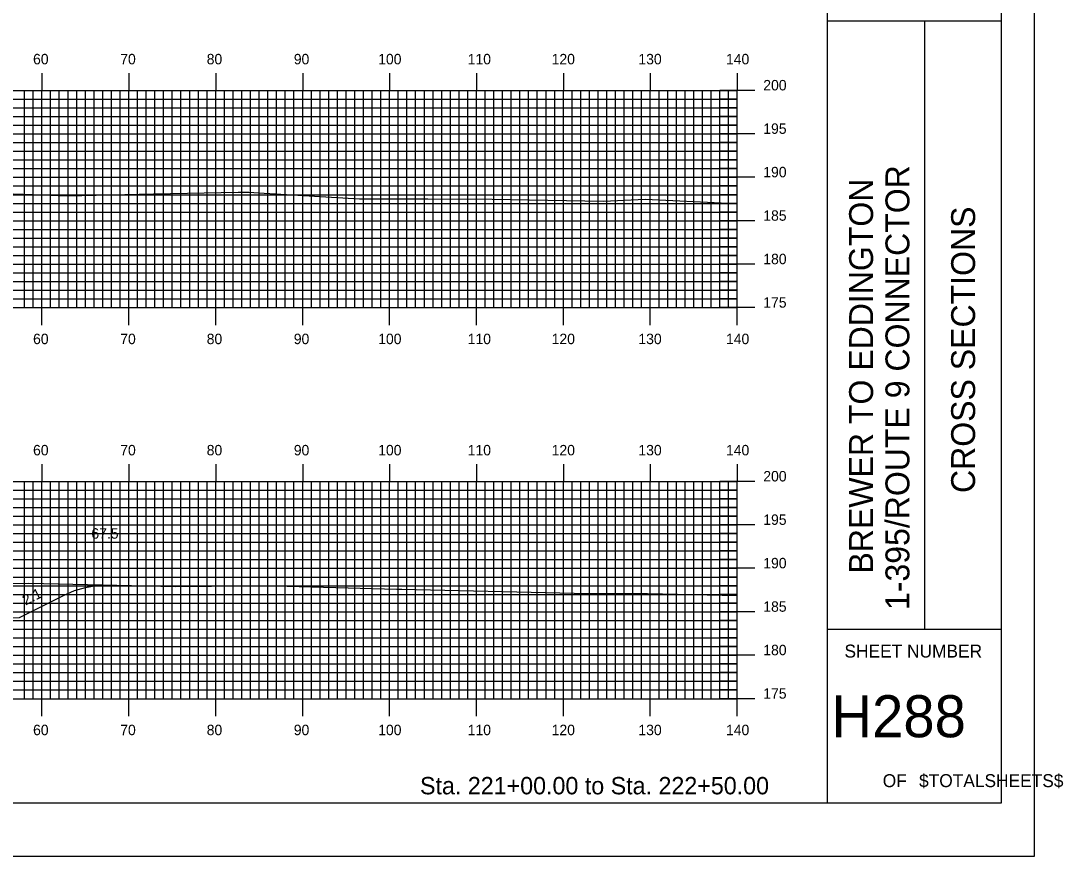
# Model space of a CAD drawing. Extents: x 1797601 to 1797944, y 442591 to 442811.
# Drawn here: x 1797824 to 1797943.9, y 442590.5 to 442686.7 of the extents above; entities that cross this region are included whole.
import ezdxf

# ---------------------------------------------------------------- set-up
doc = ezdxf.new("R2010")
doc.units = 0
for name, color, linetype in [('ANNOTATION', 7, 'Continuous'), ('BORDER', 7, 'Continuous'), ('D_Roadway_Centerline', 7, 'Continuous'), ('D_Roadway_SlopeLines', 7, 'Continuous'), ('D_Text_Standard', 7, 'Continuous'), ('H_V ANNOTATION', 7, 'Continuous'), ('MAJOR', 7, 'Continuous'), ('MINOR', 7, 'Continuous'), ('PLOT BOUNDARY', 7, 'Continuous'), ('S_Roadway_Centerline', 7, 'Continuous')]:
    doc.layers.add(name, color=color, linetype=linetype)

msp = doc.modelspace()

# ---------------------------------------------------------------- linework, layer by layer
at = {"layer": 'BORDER'}
for p, q in [((1797916.84, 442596.67), (1797916.84, 442806.67)), ((1797916.84, 442686.67), (1797936.84, 442686.67)), ((1797928.03, 442616.67), (1797928.03, 442686.67)), ((1797916.84, 442616.67), (1797936.84, 442616.67))]:
    msp.add_line(p, q, dxfattribs=at)
msp.add_lwpolyline([(1797616.84, 442596.67), (1797936.84, 442596.67), (1797936.84, 442806.67), (1797616.84, 442806.67)], close=True, dxfattribs=at)
at = {"layer": 'D_Roadway_Centerline'}
msp.add_lwpolyline([(1797698.94, 442623.65), (1797700.19, 442623.55), (1797701.44, 442623.31), (1797702.69, 442622.91), (1797703.94, 442622.36), (1797711.73, 442618.47), (1797721.64, 442618.37), (1797732.27, 442614.83), (1797736.27, 442615.83), (1797746.44, 442618.37), (1797754.44, 442618.69), (1797766.44, 442618.45), (1797778.44, 442618.21), (1797786.44, 442617.89), (1797796.62, 442615.35), (1797800.62, 442614.35), (1797811.25, 442617.89), (1797823.86, 442618.01), (1797828.94, 442620.56), (1797830.19, 442621.1), (1797831.44, 442621.48), (1797832.69, 442621.7), (1797833.94, 442621.75)], dxfattribs=at)
at = {"layer": 'D_Roadway_SlopeLines'}
msp.add_lwpolyline([(1797811.25, 442617.89), (1797823.86, 442618.01), (1797828.94, 442620.56), (1797830.19, 442621.1), (1797831.44, 442621.48), (1797832.69, 442621.7), (1797833.94, 442621.75)], dxfattribs=at)
at = {"layer": 'MAJOR'}
for p, q in [((1797826.44, 442680.67), (1797826.44, 442678.67)), ((1797836.44, 442680.67), (1797836.44, 442678.67)), ((1797846.44, 442680.67), (1797846.44, 442678.67)), ((1797856.44, 442680.67), (1797856.44, 442678.67)), ((1797866.44, 442680.67), (1797866.44, 442678.67)), ((1797876.44, 442680.67), (1797876.44, 442678.67)), ((1797886.44, 442680.67), (1797886.44, 442678.67)), ((1797896.44, 442680.67), (1797896.44, 442678.67)), ((1797906.44, 442680.67), (1797906.44, 442678.67)), ((1797626.44, 442678.67), (1797906.44, 442678.67)), ((1797626.44, 442678.67), (1797906.44, 442678.67)), ((1797826.44, 442653.67), (1797826.44, 442678.67)), ((1797836.44, 442653.67), (1797836.44, 442678.67)), ((1797846.44, 442653.67), (1797846.44, 442678.67)), ((1797856.44, 442653.67), (1797856.44, 442678.67)), ((1797866.44, 442653.67), (1797866.44, 442678.67)), ((1797876.44, 442653.67), (1797876.44, 442678.67)), ((1797886.44, 442653.67), (1797886.44, 442678.67)), ((1797896.44, 442653.67), (1797896.44, 442678.67)), ((1797908.45, 442678.67), (1797904.44, 442678.67)), ((1797906.44, 442653.67), (1797906.44, 442678.67)), ((1797906.44, 442653.67), (1797906.44, 442678.67)), ((1797626.44, 442673.67), (1797906.44, 442673.67)), ((1797908.45, 442673.67), (1797904.44, 442673.67)), ((1797626.44, 442668.67), (1797906.44, 442668.67)), ((1797908.45, 442668.67), (1797904.44, 442668.67)), ((1797626.44, 442663.67), (1797906.44, 442663.67)), ((1797908.45, 442663.67), (1797904.44, 442663.67)), ((1797626.44, 442658.67), (1797906.44, 442658.67)), ((1797908.45, 442658.67), (1797904.44, 442658.67)), ((1797626.44, 442653.67), (1797906.44, 442653.67)), ((1797626.44, 442653.67), (1797906.44, 442653.67)), ((1797826.44, 442651.66), (1797826.44, 442653.67)), ((1797836.44, 442651.66), (1797836.44, 442653.67)), ((1797846.44, 442651.66), (1797846.44, 442653.67)), ((1797856.44, 442651.66), (1797856.44, 442653.67)), ((1797866.44, 442651.66), (1797866.44, 442653.67)), ((1797876.44, 442651.66), (1797876.44, 442653.67)), ((1797886.44, 442651.66), (1797886.44, 442653.67)), ((1797896.44, 442651.66), (1797896.44, 442653.67)), ((1797908.45, 442653.67), (1797904.44, 442653.67)), ((1797906.44, 442651.66), (1797906.44, 442653.67)), ((1797826.44, 442635.67), (1797826.44, 442633.67)), ((1797836.44, 442635.67), (1797836.44, 442633.67)), ((1797846.44, 442635.67), (1797846.44, 442633.67)), ((1797856.44, 442635.67), (1797856.44, 442633.67)), ((1797866.44, 442635.67), (1797866.44, 442633.67)), ((1797876.44, 442635.67), (1797876.44, 442633.67)), ((1797886.44, 442635.67), (1797886.44, 442633.67)), ((1797896.44, 442635.67), (1797896.44, 442633.67)), ((1797906.44, 442635.67), (1797906.44, 442633.67)), ((1797626.44, 442633.67), (1797906.44, 442633.67)), ((1797626.44, 442633.67), (1797906.44, 442633.67)), ((1797826.44, 442608.67), (1797826.44, 442633.67)), ((1797836.44, 442608.67), (1797836.44, 442633.67)), ((1797846.44, 442608.67), (1797846.44, 442633.67)), ((1797856.44, 442608.67), (1797856.44, 442633.67)), ((1797866.44, 442608.67), (1797866.44, 442633.67)), ((1797876.44, 442608.67), (1797876.44, 442633.67)), ((1797886.44, 442608.67), (1797886.44, 442633.67)), ((1797896.44, 442608.67), (1797896.44, 442633.67)), ((1797908.45, 442633.67), (1797904.44, 442633.67)), ((1797906.44, 442608.67), (1797906.44, 442633.67)), ((1797906.44, 442608.67), (1797906.44, 442633.67)), ((1797626.44, 442628.67), (1797906.44, 442628.67)), ((1797908.45, 442628.67), (1797904.44, 442628.67)), ((1797626.44, 442623.67), (1797906.44, 442623.67)), ((1797908.45, 442623.67), (1797904.44, 442623.67)), ((1797626.44, 442618.67), (1797906.44, 442618.67)), ((1797908.45, 442618.67), (1797904.44, 442618.67)), ((1797626.44, 442613.67), (1797906.44, 442613.67)), ((1797908.45, 442613.67), (1797904.44, 442613.67)), ((1797626.44, 442608.67), (1797906.44, 442608.67)), ((1797626.44, 442608.67), (1797906.44, 442608.67)), ((1797826.44, 442606.66), (1797826.44, 442608.67)), ((1797836.44, 442606.66), (1797836.44, 442608.67)), ((1797846.44, 442606.66), (1797846.44, 442608.67)), ((1797856.44, 442606.66), (1797856.44, 442608.67)), ((1797866.44, 442606.66), (1797866.44, 442608.67)), ((1797876.44, 442606.66), (1797876.44, 442608.67)), ((1797886.44, 442606.66), (1797886.44, 442608.67)), ((1797896.44, 442606.66), (1797896.44, 442608.67)), ((1797908.45, 442608.67), (1797904.44, 442608.67)), ((1797906.44, 442606.66), (1797906.44, 442608.67))]:
    msp.add_line(p, q, dxfattribs=at)
at = {"layer": 'MINOR'}
for p, q in [((1797824.44, 442653.67), (1797824.44, 442678.67)), ((1797825.44, 442653.67), (1797825.44, 442678.67)), ((1797827.44, 442653.67), (1797827.44, 442678.67)), ((1797828.44, 442653.67), (1797828.44, 442678.67)), ((1797829.44, 442653.67), (1797829.44, 442678.67)), ((1797830.44, 442653.67), (1797830.44, 442678.67)), ((1797831.44, 442653.67), (1797831.44, 442678.67)), ((1797832.44, 442653.67), (1797832.44, 442678.67)), ((1797833.44, 442653.67), (1797833.44, 442678.67)), ((1797834.44, 442653.67), (1797834.44, 442678.67)), ((1797835.44, 442653.67), (1797835.44, 442678.67)), ((1797837.44, 442653.67), (1797837.44, 442678.67)), ((1797838.44, 442653.67), (1797838.44, 442678.67)), ((1797839.44, 442653.67), (1797839.44, 442678.67)), ((1797840.44, 442653.67), (1797840.44, 442678.67)), ((1797841.44, 442653.67), (1797841.44, 442678.67)), ((1797842.44, 442653.67), (1797842.44, 442678.67)), ((1797843.44, 442653.67), (1797843.44, 442678.67)), ((1797844.44, 442653.67), (1797844.44, 442678.67)), ((1797845.44, 442653.67), (1797845.44, 442678.67)), ((1797847.44, 442653.67), (1797847.44, 442678.67)), ((1797848.44, 442653.67), (1797848.44, 442678.67)), ((1797849.44, 442653.67), (1797849.44, 442678.67)), ((1797850.44, 442653.67), (1797850.44, 442678.67)), ((1797851.44, 442653.67), (1797851.44, 442678.67)), ((1797852.44, 442653.67), (1797852.44, 442678.67)), ((1797853.44, 442653.67), (1797853.44, 442678.67)), ((1797854.44, 442653.67), (1797854.44, 442678.67)), ((1797855.44, 442653.67), (1797855.44, 442678.67)), ((1797857.44, 442653.67), (1797857.44, 442678.67)), ((1797858.44, 442653.67), (1797858.44, 442678.67)), ((1797859.44, 442653.67), (1797859.44, 442678.67)), ((1797860.44, 442653.67), (1797860.44, 442678.67)), ((1797861.44, 442653.67), (1797861.44, 442678.67)), ((1797862.44, 442653.67), (1797862.44, 442678.67)), ((1797863.44, 442653.67), (1797863.44, 442678.67)), ((1797864.44, 442653.67), (1797864.44, 442678.67)), ((1797865.44, 442653.67), (1797865.44, 442678.67)), ((1797867.44, 442653.67), (1797867.44, 442678.67)), ((1797868.44, 442653.67), (1797868.44, 442678.67)), ((1797869.44, 442653.67), (1797869.44, 442678.67)), ((1797870.44, 442653.67), (1797870.44, 442678.67)), ((1797871.44, 442653.67), (1797871.44, 442678.67)), ((1797872.44, 442653.67), (1797872.44, 442678.67)), ((1797873.44, 442653.67), (1797873.44, 442678.67)), ((1797874.44, 442653.67), (1797874.44, 442678.67)), ((1797875.44, 442653.67), (1797875.44, 442678.67)), ((1797877.44, 442653.67), (1797877.44, 442678.67)), ((1797878.44, 442653.67), (1797878.44, 442678.67)), ((1797879.44, 442653.67), (1797879.44, 442678.67)), ((1797880.44, 442653.67), (1797880.44, 442678.67)), ((1797881.44, 442653.67), (1797881.44, 442678.67)), ((1797882.44, 442653.67), (1797882.44, 442678.67)), ((1797883.44, 442653.67), (1797883.44, 442678.67)), ((1797884.44, 442653.67), (1797884.44, 442678.67)), ((1797885.44, 442653.67), (1797885.44, 442678.67)), ((1797887.44, 442653.67), (1797887.44, 442678.67)), ((1797888.44, 442653.67), (1797888.44, 442678.67)), ((1797889.44, 442653.67), (1797889.44, 442678.67)), ((1797890.44, 442653.67), (1797890.44, 442678.67)), ((1797891.44, 442653.67), (1797891.44, 442678.67)), ((1797892.44, 442653.67), (1797892.44, 442678.67)), ((1797893.44, 442653.67), (1797893.44, 442678.67)), ((1797894.44, 442653.67), (1797894.44, 442678.67)), ((1797895.44, 442653.67), (1797895.44, 442678.67)), ((1797897.44, 442653.67), (1797897.44, 442678.67)), ((1797898.44, 442653.67), (1797898.44, 442678.67)), ((1797899.44, 442653.67), (1797899.44, 442678.67)), ((1797900.44, 442653.67), (1797900.44, 442678.67)), ((1797901.44, 442653.67), (1797901.44, 442678.67)), ((1797902.44, 442653.67), (1797902.44, 442678.67)), ((1797903.44, 442653.67), (1797903.44, 442678.67)), ((1797904.44, 442653.67), (1797904.44, 442678.67)), ((1797905.44, 442653.67), (1797905.44, 442678.67)), ((1797626.44, 442677.67), (1797906.44, 442677.67)), ((1797906.44, 442677.67), (1797904.44, 442677.67)), ((1797626.44, 442676.67), (1797906.44, 442676.67)), ((1797906.44, 442676.67), (1797904.44, 442676.67)), ((1797626.44, 442675.67), (1797906.44, 442675.67)), ((1797626.44, 442674.67), (1797906.44, 442674.67)), ((1797906.44, 442675.67), (1797904.44, 442675.67)), ((1797906.44, 442674.67), (1797904.44, 442674.67)), ((1797626.44, 442672.67), (1797906.44, 442672.67)), ((1797906.44, 442672.67), (1797904.44, 442672.67)), ((1797626.44, 442671.67), (1797906.44, 442671.67)), ((1797906.44, 442671.67), (1797904.44, 442671.67)), ((1797626.44, 442670.67), (1797906.44, 442670.67)), ((1797906.44, 442670.67), (1797904.44, 442670.67)), ((1797626.44, 442669.67), (1797906.44, 442669.67)), ((1797906.44, 442669.67), (1797904.44, 442669.67)), ((1797626.44, 442667.67), (1797906.44, 442667.67)), ((1797906.44, 442667.67), (1797904.44, 442667.67)), ((1797626.44, 442666.67), (1797906.44, 442666.67)), ((1797906.44, 442666.67), (1797904.44, 442666.67)), ((1797626.44, 442665.67), (1797906.44, 442665.67)), ((1797906.44, 442665.67), (1797904.44, 442665.67)), ((1797626.44, 442664.67), (1797906.44, 442664.67)), ((1797906.44, 442664.67), (1797904.44, 442664.67)), ((1797626.44, 442662.67), (1797906.44, 442662.67)), ((1797906.44, 442662.67), (1797904.44, 442662.67)), ((1797626.44, 442661.67), (1797906.44, 442661.67)), ((1797906.44, 442661.67), (1797904.44, 442661.67)), ((1797626.44, 442660.67), (1797906.44, 442660.67)), ((1797906.44, 442660.67), (1797904.44, 442660.67)), ((1797626.44, 442659.67), (1797906.44, 442659.67)), ((1797906.44, 442659.67), (1797904.44, 442659.67)), ((1797626.44, 442657.67), (1797906.44, 442657.67)), ((1797626.44, 442656.67), (1797906.44, 442656.67)), ((1797906.44, 442657.67), (1797904.44, 442657.67)), ((1797906.44, 442656.67), (1797904.44, 442656.67)), ((1797626.44, 442655.67), (1797906.44, 442655.67)), ((1797906.44, 442655.67), (1797904.44, 442655.67)), ((1797626.44, 442654.67), (1797906.44, 442654.67)), ((1797906.44, 442654.67), (1797904.44, 442654.67)), ((1797626.44, 442632.67), (1797906.44, 442632.67)), ((1797824.44, 442608.67), (1797824.44, 442633.67)), ((1797825.44, 442608.67), (1797825.44, 442633.67)), ((1797827.44, 442608.67), (1797827.44, 442633.67)), ((1797828.44, 442608.67), (1797828.44, 442633.67)), ((1797829.44, 442608.67), (1797829.44, 442633.67)), ((1797830.44, 442608.67), (1797830.44, 442633.67)), ((1797831.44, 442608.67), (1797831.44, 442633.67)), ((1797832.44, 442608.67), (1797832.44, 442633.67)), ((1797833.44, 442608.67), (1797833.44, 442633.67)), ((1797834.44, 442608.67), (1797834.44, 442633.67)), ((1797835.44, 442608.67), (1797835.44, 442633.67)), ((1797837.44, 442608.67), (1797837.44, 442633.67)), ((1797838.44, 442608.67), (1797838.44, 442633.67)), ((1797839.44, 442608.67), (1797839.44, 442633.67)), ((1797840.44, 442608.67), (1797840.44, 442633.67)), ((1797841.44, 442608.67), (1797841.44, 442633.67)), ((1797842.44, 442608.67), (1797842.44, 442633.67)), ((1797843.44, 442608.67), (1797843.44, 442633.67)), ((1797844.44, 442608.67), (1797844.44, 442633.67)), ((1797845.44, 442608.67), (1797845.44, 442633.67)), ((1797847.44, 442608.67), (1797847.44, 442633.67)), ((1797848.44, 442608.67), (1797848.44, 442633.67)), ((1797849.44, 442608.67), (1797849.44, 442633.67)), ((1797850.44, 442608.67), (1797850.44, 442633.67)), ((1797851.44, 442608.67), (1797851.44, 442633.67)), ((1797852.44, 442608.67), (1797852.44, 442633.67)), ((1797853.44, 442608.67), (1797853.44, 442633.67)), ((1797854.44, 442608.67), (1797854.44, 442633.67)), ((1797855.44, 442608.67), (1797855.44, 442633.67)), ((1797857.44, 442608.67), (1797857.44, 442633.67)), ((1797858.44, 442608.67), (1797858.44, 442633.67)), ((1797859.44, 442608.67), (1797859.44, 442633.67)), ((1797860.44, 442608.67), (1797860.44, 442633.67)), ((1797861.44, 442608.67), (1797861.44, 442633.67)), ((1797862.44, 442608.67), (1797862.44, 442633.67)), ((1797863.44, 442608.67), (1797863.44, 442633.67)), ((1797864.44, 442608.67), (1797864.44, 442633.67)), ((1797865.44, 442608.67), (1797865.44, 442633.67)), ((1797867.44, 442608.67), (1797867.44, 442633.67)), ((1797868.44, 442608.67), (1797868.44, 442633.67)), ((1797869.44, 442608.67), (1797869.44, 442633.67)), ((1797870.44, 442608.67), (1797870.44, 442633.67)), ((1797871.44, 442608.67), (1797871.44, 442633.67)), ((1797872.44, 442608.67), (1797872.44, 442633.67)), ((1797873.44, 442608.67), (1797873.44, 442633.67)), ((1797874.44, 442608.67), (1797874.44, 442633.67)), ((1797875.44, 442608.67), (1797875.44, 442633.67)), ((1797877.44, 442608.67), (1797877.44, 442633.67)), ((1797878.44, 442608.67), (1797878.44, 442633.67)), ((1797879.44, 442608.67), (1797879.44, 442633.67)), ((1797880.44, 442608.67), (1797880.44, 442633.67)), ((1797881.44, 442608.67), (1797881.44, 442633.67)), ((1797882.44, 442608.67), (1797882.44, 442633.67)), ((1797883.44, 442608.67), (1797883.44, 442633.67)), ((1797884.44, 442608.67), (1797884.44, 442633.67)), ((1797885.44, 442608.67), (1797885.44, 442633.67)), ((1797887.44, 442608.67), (1797887.44, 442633.67)), ((1797888.44, 442608.67), (1797888.44, 442633.67)), ((1797889.44, 442608.67), (1797889.44, 442633.67)), ((1797890.44, 442608.67), (1797890.44, 442633.67)), ((1797891.44, 442608.67), (1797891.44, 442633.67)), ((1797892.44, 442608.67), (1797892.44, 442633.67)), ((1797893.44, 442608.67), (1797893.44, 442633.67)), ((1797894.44, 442608.67), (1797894.44, 442633.67)), ((1797895.44, 442608.67), (1797895.44, 442633.67)), ((1797897.44, 442608.67), (1797897.44, 442633.67)), ((1797898.44, 442608.67), (1797898.44, 442633.67)), ((1797899.44, 442608.67), (1797899.44, 442633.67)), ((1797900.44, 442608.67), (1797900.44, 442633.67)), ((1797901.44, 442608.67), (1797901.44, 442633.67)), ((1797902.44, 442608.67), (1797902.44, 442633.67)), ((1797903.44, 442608.67), (1797903.44, 442633.67)), ((1797904.44, 442608.67), (1797904.44, 442633.67)), ((1797906.44, 442632.67), (1797904.44, 442632.67)), ((1797905.44, 442608.67), (1797905.44, 442633.67)), ((1797626.44, 442631.67), (1797906.44, 442631.67)), ((1797906.44, 442631.67), (1797904.44, 442631.67)), ((1797626.44, 442630.67), (1797906.44, 442630.67)), ((1797906.44, 442630.67), (1797904.44, 442630.67)), ((1797626.44, 442629.67), (1797906.44, 442629.67)), ((1797906.44, 442629.67), (1797904.44, 442629.67)), ((1797626.44, 442627.67), (1797906.44, 442627.67)), ((1797626.44, 442626.67), (1797906.44, 442626.67)), ((1797906.44, 442627.67), (1797904.44, 442627.67)), ((1797906.44, 442626.67), (1797904.44, 442626.67)), ((1797626.44, 442625.67), (1797906.44, 442625.67)), ((1797906.44, 442625.67), (1797904.44, 442625.67)), ((1797626.44, 442624.67), (1797906.44, 442624.67)), ((1797906.44, 442624.67), (1797904.44, 442624.67)), ((1797626.44, 442622.67), (1797906.44, 442622.67)), ((1797906.44, 442622.67), (1797904.44, 442622.67)), ((1797626.44, 442621.67), (1797906.44, 442621.67)), ((1797626.44, 442620.67), (1797906.44, 442620.67)), ((1797906.44, 442621.67), (1797904.44, 442621.67)), ((1797906.44, 442620.67), (1797904.44, 442620.67)), ((1797626.44, 442619.67), (1797906.44, 442619.67)), ((1797906.44, 442619.67), (1797904.44, 442619.67)), ((1797626.44, 442617.67), (1797906.44, 442617.67)), ((1797906.44, 442617.67), (1797904.44, 442617.67)), ((1797626.44, 442616.67), (1797906.44, 442616.67)), ((1797906.44, 442616.67), (1797904.44, 442616.67)), ((1797626.44, 442615.67), (1797906.44, 442615.67)), ((1797626.44, 442614.67), (1797906.44, 442614.67)), ((1797906.44, 442615.67), (1797904.44, 442615.67)), ((1797906.44, 442614.67), (1797904.44, 442614.67)), ((1797626.44, 442612.67), (1797906.44, 442612.67)), ((1797906.44, 442612.67), (1797904.44, 442612.67)), ((1797626.44, 442611.67), (1797906.44, 442611.67)), ((1797906.44, 442611.67), (1797904.44, 442611.67)), ((1797626.44, 442610.67), (1797906.44, 442610.67)), ((1797906.44, 442610.67), (1797904.44, 442610.67)), ((1797626.44, 442609.67), (1797906.44, 442609.67)), ((1797906.44, 442609.67), (1797904.44, 442609.67))]:
    msp.add_line(p, q, dxfattribs=at)
at = {"layer": 'PLOT BOUNDARY'}
msp.add_lwpolyline([(1797600.66, 442590.55), (1797940.66, 442590.55), (1797940.66, 442810.55), (1797600.66, 442810.55)], close=True, dxfattribs=at)
at = {"layer": 'S_Roadway_Centerline'}
for points in [[(1797815.1, 442667.03), (1797826.56, 442666.64), (1797828.3, 442666.58), (1797829.39, 442666.54), (1797839.27, 442666.75), (1797849.03, 442666.94), (1797850.24, 442666.95), (1797852.01, 442666.86), (1797862.99, 442666.2), (1797870.86, 442666.21), (1797878.26, 442666.14), (1797891.05, 442665.93), (1797895.83, 442666.17), (1797905.4, 442665.68), (1797906.44, 442665.67)], [(1797815.49, 442621.88), (1797824.93, 442621.95), (1797841.8, 442621.58), (1797845.94, 442621.6), (1797853.25, 442621.64), (1797867.28, 442621.28), (1797867.57, 442621.29), (1797867.84, 442621.27), (1797887.69, 442620.81), (1797896.11, 442620.76), (1797906.44, 442620.55)]]:
    msp.add_lwpolyline(points, dxfattribs=at)

# ---------------------------------------------------------------- texts
at = {"layer": 'ANNOTATION'}
msp.add_text('2:1', height=1.2, rotation=26.5651, dxfattribs=at).set_placement((1797824.55, 442619.39))
at = {"layer": 'BORDER'}
for s, p in [('1-395/ROUTE 9 CONNECTOR', (1797926.25, 442618.87)), ('BREWER TO EDDINGTON', (1797922.07, 442623.07)), ('CROSS SECTIONS', (1797933.81, 442632.34))]:
    msp.add_text(s, height=2.7557, rotation=90, dxfattribs=at).set_placement(p)
for s, height, p in [('SHEET NUMBER', 1.4905, (1797918.78, 442613.4)), ('H288', 4.839, (1797917.28, 442604.23)), ('OF', 1.491, (1797923.18, 442598.49)), ('$TOTALSHEETS$', 1.4905, (1797927.36, 442598.49))]:
    msp.add_text(s, height=height, dxfattribs=at).set_placement(p)
at = {"layer": 'D_Text_Standard'}
msp.add_text("67.5'", height=1.2, dxfattribs=at).set_placement((1797832.13, 442627.08))
at = {"layer": 'H_V ANNOTATION'}
for s, height, p in [('60', 1.2, (1797825.42, 442681.67)), ('70', 1.2, (1797835.45, 442681.67)), ('80', 1.2, (1797845.4, 442681.67)), ('90', 1.2, (1797855.42, 442681.67)), ('100', 1.2, (1797865.13, 442681.67)), ('110', 1.2, (1797875.43, 442681.67)), ('120', 1.2, (1797885.09, 442681.67)), ('130', 1.2, (1797895.07, 442681.67)), ('140', 1.2, (1797905.15, 442681.67)), ('200', 1.2, (1797909.44, 442678.67)), ('195', 1.2, (1797909.44, 442673.67)), ('190', 1.2, (1797909.44, 442668.67)), ('185', 1.2, (1797909.44, 442663.67)), ('180', 1.2, (1797909.44, 442658.67)), ('175', 1.2, (1797909.44, 442653.67)), ('60', 1.2, (1797825.42, 442649.47)), ('70', 1.2, (1797835.45, 442649.47)), ('80', 1.2, (1797845.4, 442649.47)), ('90', 1.2, (1797855.42, 442649.47)), ('100', 1.2, (1797865.13, 442649.47)), ('110', 1.2, (1797875.43, 442649.47)), ('120', 1.2, (1797885.09, 442649.47)), ('130', 1.2, (1797895.07, 442649.47)), ('140', 1.2, (1797905.15, 442649.47)), ('60', 1.2, (1797825.42, 442636.67)), ('70', 1.2, (1797835.45, 442636.67)), ('80', 1.2, (1797845.4, 442636.67)), ('90', 1.2, (1797855.42, 442636.67)), ('100', 1.2, (1797865.13, 442636.67)), ('110', 1.2, (1797875.43, 442636.67)), ('120', 1.2, (1797885.09, 442636.67)), ('130', 1.2, (1797895.07, 442636.67)), ('140', 1.2, (1797905.15, 442636.67)), ('200', 1.2, (1797909.44, 442633.67)), ('195', 1.2, (1797909.44, 442628.67)), ('190', 1.2, (1797909.44, 442623.67)), ('185', 1.2, (1797909.44, 442618.67)), ('180', 1.2, (1797909.44, 442613.67)), ('175', 1.2, (1797909.44, 442608.67)), ('60', 1.2, (1797825.42, 442604.47)), ('70', 1.2, (1797835.45, 442604.47)), ('80', 1.2, (1797845.4, 442604.47)), ('90', 1.2, (1797855.42, 442604.47)), ('100', 1.2, (1797865.13, 442604.47)), ('110', 1.2, (1797875.43, 442604.47)), ('120', 1.2, (1797885.09, 442604.47)), ('130', 1.2, (1797895.07, 442604.47)), ('140', 1.2, (1797905.15, 442604.47)), ('Sta. 221+00.00 to Sta. 222+50.00', 2.0004, (1797869.94, 442597.66))]:
    msp.add_text(s, height=height, dxfattribs=at).set_placement(p)

doc.saveas('drawing.dxf')
